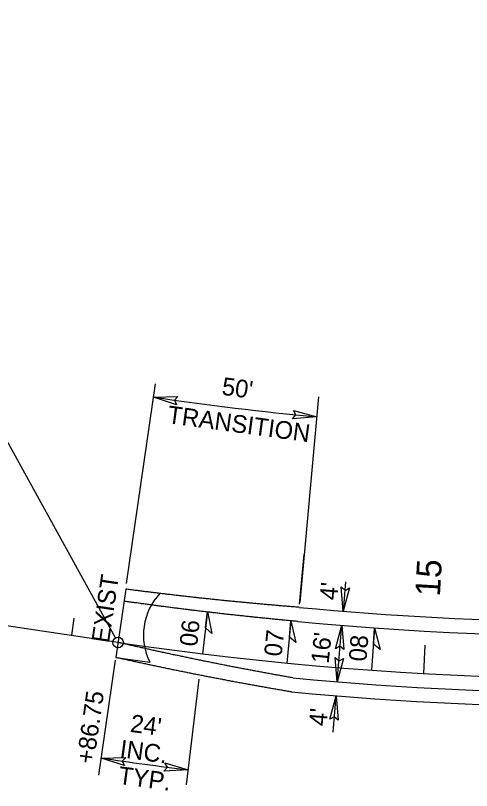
# Model space of a CAD drawing. Extents: x 2242984 to 2250974, y 661492 to 664681.
# Drawn here: x 2248067.7 to 2248196.5, y 663147.6 to 663366.5 of the extents above; entities that cross this region are included whole.
import ezdxf

# ---------------------------------------------------------------- set-up
doc = ezdxf.new("R2010")
doc.units = 0
for name, color, linetype in [('Prop Dimension', 7, 'Continuous'), ('Prop Dimension Text', 7, 'Continuous'), ('Prop EOT', 7, 'Continuous'), ('Prop Horizontal Alignment', 7, 'Continuous'), ('Prop Horizontal Alignment Station Label', 7, 'Continuous'), ('Prop Horizontal Alignment Tick Label', 7, 'Continuous'), ('Prop Horizontal Alignment Tick Large', 7, 'Continuous'), ('Prop Horizontal Alignment Tick Small', 7, 'Continuous'), ('Prop Paved Shoulder', 7, 'Continuous'), ('Prop Shade Medium', 7, 'Continuous'), ('Prop Superelevation  Arrow CELL', 7, 'Continuous'), ('Prop Superelevation Label', 7, 'Continuous'), ('Prop Terminator CELL', 7, 'Continuous')]:
    doc.layers.add(name, color=color, linetype=linetype)

msp = doc.modelspace()

# ---------------------------------------------------------------- linework, layer by layer
at = {"layer": 'Prop Dimension'}
for p, q in [((2248099.11, 663206.11), (2248107.27, 663262.49)), ((2248153.32, 663258.78), (2248147.98, 663200.69)), ((2248147.94, 663200.27), (2248149.23, 663214.3)), ((2248160.9, 663206.6), (2248160.22, 663198.27)), ((2248158.59, 663178.34), (2248159.89, 663194.29)), ((2248091.28, 663152.01), (2248095.98, 663184.49)), ((2248115.98, 663149.26), (2248119.62, 663179.05)), ((2248157.43, 663164.13), (2248158.27, 663174.35))]:
    msp.add_line(p, q, dxfattribs=at)
for radius, start, end in [(890, 261.58234, 264.57073), (993, 261.60136, 263.02909)]:
    msp.add_arc((2248237.01, 664139.15), radius, start, end, dxfattribs=at)
at = {"layer": 'Prop EOT'}
for radius, start, end in [(948, 264.58168, 292.13013), (964, 264.58443, 275.75472)]:
    msp.add_arc((2248237.01, 664139.15), radius, start, end, dxfattribs=at)
for points in [[(2248147.49, 663195.38), (2248146.83, 663195.44), (2248146.16, 663195.5), (2248145.49, 663195.56), (2248144.83, 663195.63), (2248144.16, 663195.69), (2248143.5, 663195.75), (2248142.83, 663195.81), (2248142.17, 663195.88), (2248141.5, 663195.94), (2248140.84, 663196.01), (2248140.17, 663196.07), (2248139.51, 663196.14), (2248138.84, 663196.2), (2248138.18, 663196.27), (2248137.52, 663196.34), (2248136.85, 663196.4), (2248136.19, 663196.47), (2248135.52, 663196.54), (2248134.86, 663196.61), (2248134.19, 663196.68), (2248133.53, 663196.75), (2248132.86, 663196.82), (2248132.2, 663196.89), (2248131.53, 663196.96), (2248130.87, 663197.03), (2248130.21, 663197.1), (2248129.54, 663197.17), (2248128.88, 663197.25), (2248128.21, 663197.32), (2248127.55, 663197.39), (2248126.89, 663197.47), (2248126.22, 663197.54), (2248125.56, 663197.62), (2248124.89, 663197.69), (2248124.23, 663197.77), (2248123.57, 663197.85), (2248122.9, 663197.92), (2248122.24, 663198), (2248121.58, 663198.08), (2248120.91, 663198.16), (2248120.25, 663198.24), (2248119.59, 663198.32), (2248118.92, 663198.4), (2248118.26, 663198.48), (2248117.6, 663198.56), (2248116.93, 663198.64), (2248116.27, 663198.72), (2248115.61, 663198.8), (2248114.94, 663198.89), (2248114.28, 663198.97), (2248113.62, 663199.05), (2248112.96, 663199.14), (2248112.29, 663199.22), (2248111.63, 663199.31), (2248110.97, 663199.39), (2248110.3, 663199.48), (2248109.64, 663199.56), (2248108.98, 663199.65), (2248108.32, 663199.74), (2248107.65, 663199.83), (2248106.99, 663199.91), (2248106.33, 663200), (2248105.67, 663200.09), (2248105.01, 663200.18), (2248104.34, 663200.27), (2248103.68, 663200.36), (2248103.02, 663200.45), (2248102.36, 663200.55), (2248101.7, 663200.64), (2248101.03, 663200.73), (2248100.37, 663200.82), (2248099.71, 663200.92), (2248098.39, 663201.11)], [(2248146.03, 663179.45), (2248145.36, 663179.57), (2248144.69, 663179.69), (2248144.02, 663179.81), (2248143.34, 663179.92), (2248142.67, 663180.04), (2248142, 663180.17), (2248141.33, 663180.29), (2248140.66, 663180.41), (2248139.99, 663180.53), (2248139.32, 663180.65), (2248138.65, 663180.78), (2248137.98, 663180.9), (2248137.31, 663181.02), (2248136.64, 663181.15), (2248135.97, 663181.27), (2248135.3, 663181.4), (2248134.63, 663181.52), (2248133.96, 663181.65), (2248133.29, 663181.77), (2248132.63, 663181.9), (2248131.96, 663182.03), (2248131.29, 663182.16), (2248130.62, 663182.29), (2248129.95, 663182.42), (2248129.28, 663182.54), (2248128.61, 663182.67), (2248127.95, 663182.8), (2248127.28, 663182.94), (2248126.61, 663183.07), (2248125.94, 663183.2), (2248125.27, 663183.33), (2248124.61, 663183.46), (2248123.94, 663183.6), (2248123.27, 663183.73), (2248122.61, 663183.86), (2248121.94, 663184), (2248121.27, 663184.13), (2248120.61, 663184.27), (2248119.94, 663184.41), (2248119.27, 663184.54), (2248118.61, 663184.68), (2248117.94, 663184.82), (2248117.27, 663184.95), (2248116.61, 663185.09), (2248115.94, 663185.23), (2248115.28, 663185.37), (2248114.61, 663185.51), (2248113.95, 663185.65), (2248113.28, 663185.79), (2248112.62, 663185.93), (2248111.95, 663186.07), (2248111.29, 663186.22), (2248110.62, 663186.36), (2248109.96, 663186.5), (2248109.29, 663186.64), (2248108.63, 663186.79), (2248107.96, 663186.93), (2248107.3, 663187.08), (2248106.64, 663187.22), (2248105.97, 663187.37), (2248105.31, 663187.51), (2248104.65, 663187.66), (2248103.98, 663187.81), (2248103.32, 663187.96), (2248102.66, 663188.1), (2248101.99, 663188.25), (2248101.33, 663188.4), (2248100.67, 663188.55), (2248100.01, 663188.7), (2248099.34, 663188.85), (2248098.68, 663189), (2248098.02, 663189.15), (2248096.7, 663189.46)]]:
    msp.add_spline(points, degree=3, dxfattribs=at)
at = {"layer": 'Prop Horizontal Alignment'}
msp.add_line((2248096.71, 663189.45), (2247556.64, 663269.24), dxfattribs=at)
msp.add_arc((2248237.01, 664139.15), 960, 261.59641, 292.13013, dxfattribs=at)
at = {"layer": 'Prop Horizontal Alignment Station Label'}
msp.add_line((2248095.99, 663190.77), (2247999.07, 663366.52), dxfattribs=at)
msp.add_circle((2248096.71, 663189.45), 1.5, dxfattribs=at)
at = {"layer": 'Prop Horizontal Alignment Tick Large'}
msp.add_line((2248182.99, 663180.67), (2248183.44, 663188.65), dxfattribs=at)
at = {"layer": 'Prop Horizontal Alignment Tick Small'}
msp.add_line((2248083.61, 663191.39), (2248084.34, 663196.34), dxfattribs=at)
at = {"layer": 'Prop Paved Shoulder'}
for radius, start, end in [(944, 264.58097, 283.54456), (968, 264.58516, 275.75472)]:
    msp.add_arc((2248237.01, 664139.15), radius, start, end, dxfattribs=at)
for points in [[(2248147.86, 663199.37), (2248147.2, 663199.42), (2248146.53, 663199.47), (2248145.87, 663199.52), (2248145.21, 663199.58), (2248144.54, 663199.63), (2248143.88, 663199.69), (2248143.22, 663199.74), (2248142.55, 663199.8), (2248141.89, 663199.85), (2248141.23, 663199.91), (2248140.56, 663199.97), (2248139.9, 663200.03), (2248139.24, 663200.08), (2248138.58, 663200.14), (2248137.91, 663200.2), (2248137.25, 663200.26), (2248136.59, 663200.32), (2248135.93, 663200.38), (2248135.26, 663200.44), (2248134.6, 663200.5), (2248133.94, 663200.57), (2248133.27, 663200.63), (2248132.61, 663200.69), (2248131.95, 663200.75), (2248131.29, 663200.82), (2248130.63, 663200.88), (2248129.96, 663200.95), (2248129.3, 663201.01), (2248128.64, 663201.08), (2248127.98, 663201.14), (2248127.31, 663201.21), (2248126.65, 663201.28), (2248125.99, 663201.34), (2248125.33, 663201.41), (2248124.67, 663201.48), (2248124, 663201.55), (2248123.34, 663201.62), (2248122.68, 663201.69), (2248122.02, 663201.76), (2248121.36, 663201.83), (2248120.69, 663201.9), (2248120.03, 663201.97), (2248119.37, 663202.04), (2248118.71, 663202.12), (2248118.05, 663202.19), (2248117.39, 663202.26), (2248116.72, 663202.34), (2248116.06, 663202.41), (2248115.4, 663202.49), (2248114.74, 663202.56), (2248114.08, 663202.64), (2248113.42, 663202.71), (2248112.76, 663202.79), (2248112.09, 663202.87), (2248111.43, 663202.95), (2248110.77, 663203.02), (2248110.11, 663203.1), (2248109.45, 663203.18), (2248108.79, 663203.26), (2248108.13, 663203.34), (2248107.47, 663203.42), (2248106.81, 663203.5), (2248106.15, 663203.58), (2248105.49, 663203.67), (2248104.82, 663203.75), (2248104.16, 663203.83), (2248103.5, 663203.92), (2248102.84, 663204), (2248102.18, 663204.08), (2248101.52, 663204.17), (2248100.86, 663204.25), (2248100.2, 663204.34), (2248098.88, 663204.51)], [(2248145.66, 663175.47), (2248144.99, 663175.58), (2248144.31, 663175.7), (2248143.64, 663175.81), (2248142.97, 663175.93), (2248142.29, 663176.04), (2248141.62, 663176.16), (2248140.94, 663176.28), (2248140.27, 663176.39), (2248139.6, 663176.51), (2248138.92, 663176.63), (2248138.25, 663176.75), (2248137.58, 663176.87), (2248136.9, 663176.99), (2248136.23, 663177.11), (2248135.56, 663177.23), (2248134.89, 663177.35), (2248134.21, 663177.48), (2248133.54, 663177.6), (2248132.87, 663177.72), (2248132.2, 663177.84), (2248131.52, 663177.97), (2248130.85, 663178.09), (2248130.18, 663178.22), (2248129.51, 663178.34), (2248128.84, 663178.47), (2248128.17, 663178.59), (2248127.49, 663178.72), (2248126.82, 663178.85), (2248126.15, 663178.98), (2248125.48, 663179.1), (2248124.81, 663179.23), (2248124.14, 663179.36), (2248123.47, 663179.49), (2248122.8, 663179.62), (2248122.13, 663179.75), (2248121.46, 663179.88), (2248120.79, 663180.01), (2248120.12, 663180.14), (2248119.45, 663180.28), (2248118.78, 663180.41), (2248118.11, 663180.54), (2248117.44, 663180.68), (2248116.77, 663180.81), (2248116.1, 663180.95), (2248115.43, 663181.08), (2248114.76, 663181.22), (2248114.09, 663181.35), (2248113.43, 663181.49), (2248112.76, 663181.63), (2248112.09, 663181.76), (2248111.42, 663181.9), (2248110.75, 663182.04), (2248110.08, 663182.18), (2248109.42, 663182.32), (2248108.75, 663182.46), (2248108.08, 663182.6), (2248107.41, 663182.74), (2248106.75, 663182.88), (2248106.08, 663183.02), (2248105.41, 663183.16), (2248104.75, 663183.3), (2248104.08, 663183.45), (2248103.41, 663183.59), (2248102.75, 663183.74), (2248102.08, 663183.88), (2248101.41, 663184.02), (2248100.75, 663184.17), (2248100.08, 663184.32), (2248099.42, 663184.46), (2248098.75, 663184.61), (2248098.08, 663184.76), (2248097.42, 663184.9), (2248096.09, 663185.2)]]:
    msp.add_spline(points, degree=3, dxfattribs=at)
at = {"layer": 'Prop Shade Medium'}
for p, q in [((2248098.88, 663204.51), (2248096.08, 663185.2)), ((2248108.47, 663203.24), (2248098.88, 663204.51)), ((2248096.08, 663185.2), (2248105.65, 663183.85))]:
    msp.add_line(p, q, dxfattribs=at)
msp.add_arc((2248121.06, 663191.51), 17.21, 137.0165, 206.4315, dxfattribs=at)
at = {"layer": 'Prop Superelevation  Arrow CELL'}
for p, q in [((2248121.96, 663198.15), (2248120.5, 663186.24)), ((2248145.51, 663195.57), (2248144.36, 663183.63)), ((2248169.13, 663193.58), (2248168.27, 663181.61))]:
    msp.add_line(p, q, dxfattribs=at)
for points in [[(2248121.96, 663198.15), (2248123.21, 663191.96), (2248121.4, 663193.56)], [(2248145.51, 663195.57), (2248146.93, 663189.41), (2248145.07, 663190.97)], [(2248169.13, 663193.58), (2248170.7, 663187.45), (2248168.8, 663188.97)]]:
    msp.add_lwpolyline(points, close=True, dxfattribs=at)
at = {"layer": 'Prop Terminator CELL'}
for points in [[(2248113.23, 663256.6), (2248106.73, 663258.73), (2248113.62, 663258.93), (2248112.59, 663257.87)], [(2248146.19, 663254.93), (2248152.8, 663253.14), (2248145.93, 663252.59), (2248146.9, 663253.7)], [(2248162.01, 663204.89), (2248160.22, 663198.27), (2248159.66, 663205.15), (2248160.78, 663204.17)], [(2248158.1, 663187.68), (2248159.89, 663194.29), (2248160.45, 663187.42), (2248159.33, 663188.39)], [(2248160.39, 663184.95), (2248158.59, 663178.34), (2248158.04, 663185.21), (2248159.15, 663184.24)], [(2248156.47, 663167.74), (2248158.27, 663174.35), (2248158.82, 663167.48), (2248157.71, 663168.46)], [(2248098.48, 663154.66), (2248091.97, 663156.8), (2248098.86, 663156.99), (2248097.84, 663155.93)], [(2248109.94, 663155.46), (2248116.5, 663153.49), (2248109.61, 663153.12), (2248110.61, 663154.21)]]:
    msp.add_lwpolyline(points, close=True, dxfattribs=at)

# ---------------------------------------------------------------- texts
at = {"layer": 'Prop Dimension'}
for s, rotation, p in [('+86.75', 81.7657, (2248089.81, 663154.96)), ("24'", 352.3152, (2248099.94, 663164.22)), ('INC.', 352.3152, (2248097, 663157.05)), ('TYP.', 352.3152, (2248096.55, 663149.54))]:
    msp.add_text(s, height=5, rotation=rotation, dxfattribs=at).set_placement(p)
at = {"layer": 'Prop Dimension Text'}
for s, rotation, p in [("50'", 352.3152, (2248125.78, 663259.43)), ('TRANSITION', 352.3152, (2248110.43, 663251.41)), ("4'", 85.334, (2248158.6, 663201.25)), ("16'", 84.0244, (2248156.14, 663183.33)), ("4'", 85.334, (2248155.56, 663165.69))]:
    msp.add_text(s, height=5, rotation=rotation, dxfattribs=at).set_placement(p)
at = {"layer": 'Prop Horizontal Alignment Tick Label'}
msp.add_text('15', height=7, rotation=86.7742, dxfattribs=at).set_placement((2248187.56, 663202.34))
at = {"layer": 'Prop Superelevation Label'}
for s, rotation, p in [('EXIST', 81.5964, (2248094.11, 663189.1)), ('06', 83.9839, (2248119.01, 663188.17)), ('07', 83.9839, (2248142.85, 663185.32)), ('08', 85.4163, (2248166.8, 663183.95))]:
    msp.add_text(s, height=5, rotation=rotation, dxfattribs=at).set_placement(p)

doc.saveas('drawing.dxf')
